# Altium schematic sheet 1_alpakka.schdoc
size 429 x 307 mm; Symbol: Sheet-Symbol_A3; Device: Sheet-Symbol_A3; Company: 嘉立创EDA; Version: V1.0; Page Size: A3; @Project Name: alpakka_qk; @Page Count: 1; @Update Date: 2025-06-17; @Create Date: 2025-06-03; @Schematic Name: alpakka_1; @Page No: 1; @Page Name: alpakka; Title Block Position: 3; Width: 1655; Height: 1170; Region Start: 1; X Region Count: 6; Y Region Count: 4; Blade Width: 10; @Board Name: alpakka_1; @Create Time: 09:50:37; @Update Time: 01:17:22
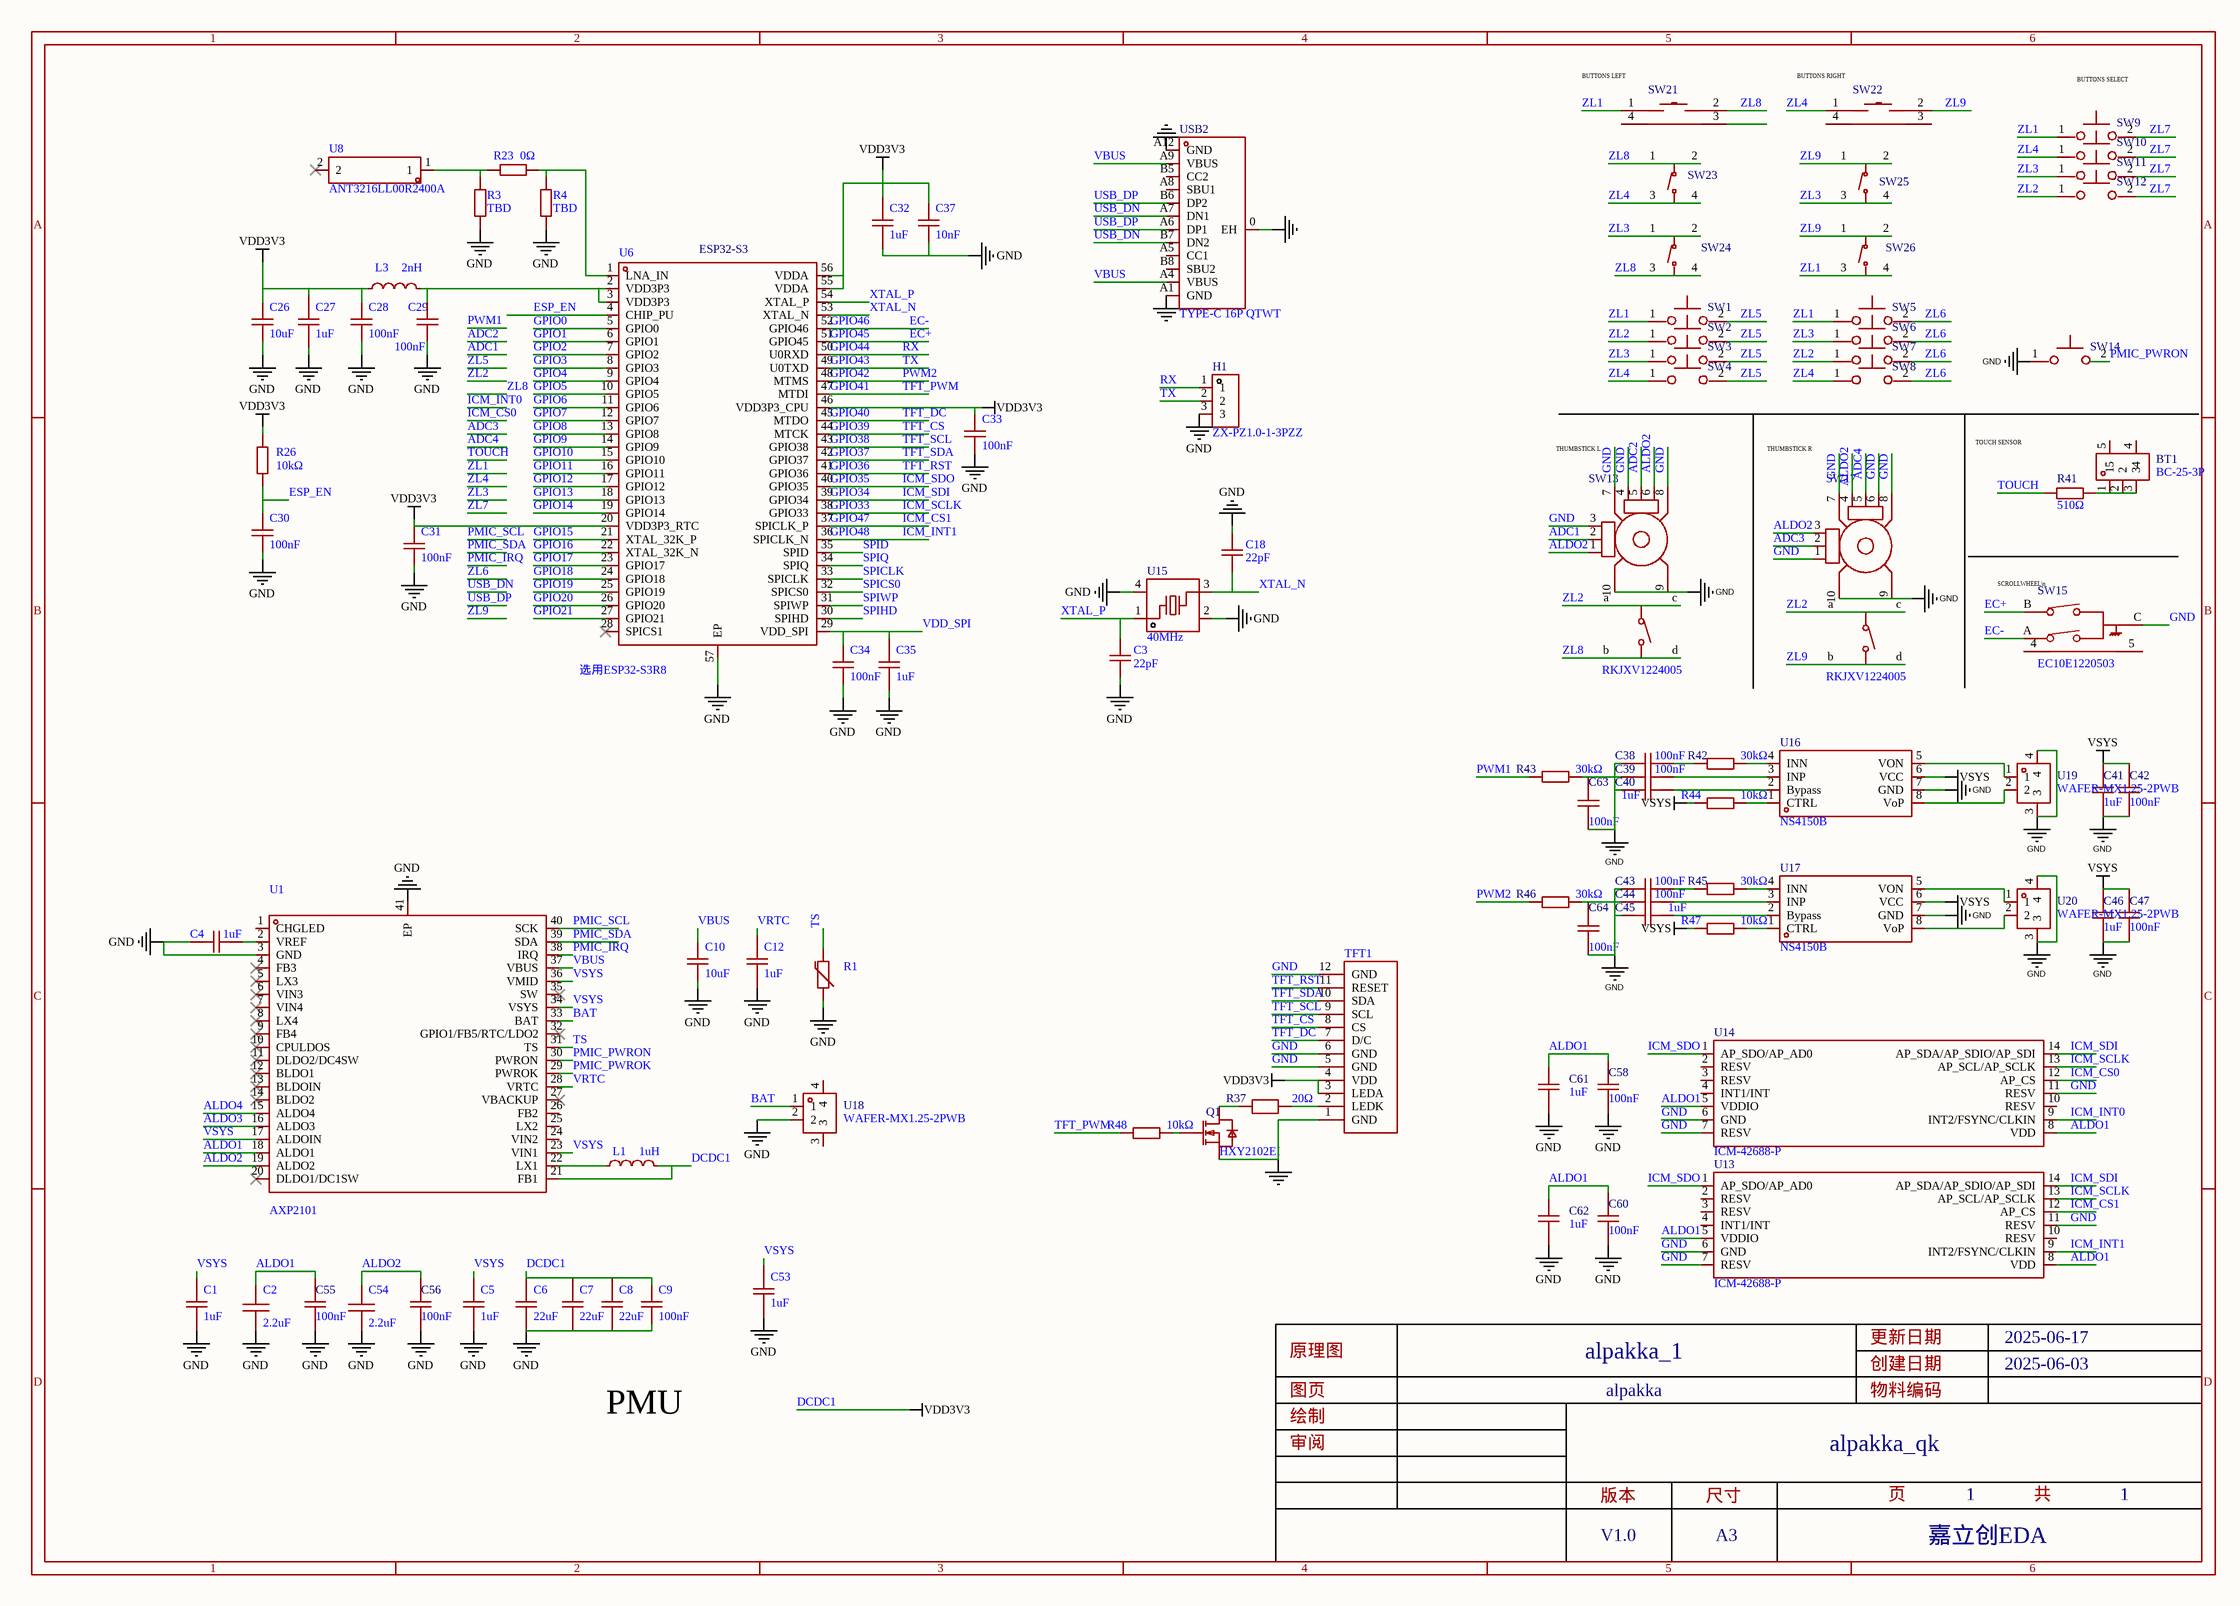
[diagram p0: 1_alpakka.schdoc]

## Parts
BT1  BC-25-3P  [CONN-SMD_BC-25-3P]
C1  1uF  [C0402]
C2  value 2.2uF  [C0402]
C3  22pF  [C0402]
C4  1uF  [C0402]
C5  1uF  [C0402]
C6  22uF  [C0603]
C7  22uF  [C0603]
C8  22uF  [C0603]
C9  100nF  [C0402]
C10  10uF  [C0402]
C12  1uF  [C0402]
C18  22pF  [C0402]
C26  10uF  [C0402]
C27  1uF  [C0402]
C28  100nF  [C0402]
C29  100nF  [C0402]
C30  100nF  [C0402]
C31  100nF  [C0402]
C32  1uF  [C0402]
C33  100nF  [C0402]
C34  100nF  [C0402]
C35  1uF  [C0402]
C37  10nF  [C0402]
C38  100nF  [C0402]
C39  100nF  [C0402]
C40  1uF  [C0402]
C41  1uF  [C0402]
C42  100nF  [C0402]
C43  100nF  [C0402]
C44  100nF  [C0402]
C45  1uF  [C0402]
C46  1uF  [C0402]
C47  100nF  [C0402]
C53  1uF  [C0402]
C54  value 2.2uF  [C0402]
C55  100nF  [C0402]
C56  100nF  [C0402]
C58  100nF  [C0402]
C60  100nF  [C0402]
C61  1uF  [C0402]
C62  1uF  [C0402]
C63  100nF  [C0402]
C64  100nF  [C0402]
H1  ZX-PZ1.0-1-3PZZ  [HDR-TH_3P-P1.00-V-M-3]
L1  1uH  [IND-SMD_L2.5-W2.0_WPN252012H]
L3  2nH  [L0402]
Q1  HXY2102EI  [SOT-323-3_L2.1-W1.3-P1.30-LS2.3-BR]
R1  NCP18XH103F03RB  [R0603]  (value not drawn)
R3  TBD  [R0402]
R4  TBD  [R0402]
R23  0Ω  [R0402]
R26  10kΩ  [R0402]
R37  20Ω  [R0402]
R41  510Ω  [R0402]
R42  30kΩ  [R0402]
R43  30kΩ  [R0402]
R44  10kΩ  [R0402]
R45  30kΩ  [R0402]
R46  30kΩ  [R0402]
R47  10kΩ  [R0402]
R48  10kΩ  [R0402]
SW1  SKPMAME010  [KEY-SMD_2P-L6.0-W6.0-P6.00]  (value not drawn)
SW2  SKPMAME010  [KEY-SMD_2P-L6.0-W6.0-P6.00]  (value not drawn)
SW3  SKPMAME010  [KEY-SMD_2P-L6.0-W6.0-P6.00]  (value not drawn)
SW4  SKPMAME010  [KEY-SMD_2P-L6.0-W6.0-P6.00]  (value not drawn)
SW5  SKPMAME010  [KEY-SMD_2P-L6.0-W6.0-P6.00]  (value not drawn)
SW6  SKPMAME010  [KEY-SMD_2P-L6.0-W6.0-P6.00]  (value not drawn)
SW7  SKPMAME010  [KEY-SMD_2P-L6.0-W6.0-P6.00]  (value not drawn)
SW8  SKPMAME010  [KEY-SMD_2P-L6.0-W6.0-P6.00]  (value not drawn)
SW9  SKPMAME010  [KEY-SMD_2P-L6.0-W6.0-P6.00]  (value not drawn)
SW10  SKPMAME010  [KEY-SMD_2P-L6.0-W6.0-P6.00]  (value not drawn)
SW11  SKPMAME010  [KEY-SMD_2P-L6.0-W6.0-P6.00]  (value not drawn)
SW12  SKPMAME010  [KEY-SMD_2P-L6.0-W6.0-P6.00]  (value not drawn)
SW13  RKJXV1224005  [SW-TH_RKJXV1224005]
SW14  SKPMAME010  [KEY-SMD_2P-L6.0-W6.0-P6.00]  (value not drawn)
SW15  EC10E1220503  [SW-TH_EC10EXXXXXXX]
SW17  RKJXV1224005  [SW-TH_RKJXV1224005]
SW21  SKHHLNA010  [KEY-TH_SKHHLNA010]  (value not drawn)
SW22  SKHHLNA010  [KEY-TH_SKHHLNA010]  (value not drawn)
SW23  TS-1187A-B-A-B  [SW-SMD_4P-L5.1-W5.1-P3.70-LS6.5-TL_H1.5]  (value not drawn)
SW24  TS-1187A-B-A-B  [SW-SMD_4P-L5.1-W5.1-P3.70-LS6.5-TL_H1.5]  (value not drawn)
SW25  TS-1187A-B-A-B  [SW-SMD_4P-L5.1-W5.1-P3.70-LS6.5-TL_H1.5]  (value not drawn)
SW26  TS-1187A-B-A-B  [SW-SMD_4P-L5.1-W5.1-P3.70-LS6.5-TL_H1.5]  (value not drawn)
TFT1  tft  [0.71圆tft]  (value not drawn)
U1  (no value)  [QFN-40_L5.0-W5.0-P0.40-TL-EP3.4]
U6  ESP32-S3  [QFN-56_L7.0-W7.0-P0.40-TL-EP4.0]
U8  ANT3216LL00R2400A  [ANT-SMD_L3.2-W1.6]
U13  ICM-42688-P  [LGA-14_L3.0-W2.5-P0.50-TL]
U14  ICM-42688-P  [LGA-14_L3.0-W2.5-P0.50-TL]
U15  40MHz  [CRYSTAL-SMD_4P-L2.5-W2.0-BL]
U16  NS4150B  [MSOP-8_L3.0-W3.0-P0.65-LS5.0-BL]
U17  NS4150B  [MSOP-8_L3.0-W3.0-P0.65-LS5.0-BL]
U18  WAFER-MX1.25-2PWB  [CONN-SMD_2P-P1.25_XUNPU_WAFER-MX1.25-2PWB]
U19  WAFER-MX1.25-2PWB  [CONN-SMD_2P-P1.25_XUNPU_WAFER-MX1.25-2PWB]
U20  WAFER-MX1.25-2PWB  [CONN-SMD_2P-P1.25_XUNPU_WAFER-MX1.25-2PWB]
USB2  TYPE-C 16P QTWT  [USB-TYPE-C-SMD_TYPE-C-16P-QTWT]

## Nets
DCDC1: C6.2 C7.2 C8.2 C9.2 C26.2 C27.2 C28.2 C31.2 C32.2 C33.2 C37.2 L1.2 L3.1 R26.2 TFT1.3(LEDA) TFT1.4(VDD) U1.21(FB1) U6.20(VDD3P3_RTC) U6.46(VDD3P3_CPU) U6.55(VDDA) U6.56(VDDA)  [also labelled VDD3V3]
GND: C1.1 C2.1 C3.1 C4.1 C5.1 C6.1 C7.1 C8.1 C9.1 C10.1 C12.1 C18.2 C26.1 C27.1 C28.1 C29.1 C30.1 C31.1 C32.1 C33.1 C34.1 C35.1 C37.1 C38.1 C40.2 C41.1 C42.1 C43.1 C45.2 C46.1 C47.1 C53.1 C54.1 C55.1 C56.1 C58.1 C60.1 C61.1 C62.1 C63.1 C64.1 H1.3 Q1.2(S) R1.2 R3.1 R4.1 SW13.3(A) SW13.4(A) SW13.7(GND) SW13.8(GND) SW13.9(GND) SW13.10(GND) SW14.1 SW15.C SW17.1(B) SW17.6(B) SW17.7(GND) SW17.8(GND) SW17.9(GND) SW17.10(GND) TFT1.1(GND) TFT1.5(GND) TFT1.6(GND) TFT1.12(GND) U1.3(GND) U1.41(EP) U6.57(EP) U13.6(GND) U13.7(RESV) U13.11(RESV) U14.6(GND) U14.7(RESV) U14.11(RESV) U15.2(GND) U15.4(GND) U16.7(GND) U17.7(GND) U18.2 U19.3 U19.4 U20.3 U20.4 USB2.0(EH) USB2.A1(GND) USB2.A12(GND)
VSYS: C1.2 C5.2 C41.2 C42.2 C46.2 C47.2 C53.2 R44.1 R47.1 U1.17(ALDOIN) U1.23(VIN1) U1.34(VSYS) U1.36(VMID) U16.6(VCC) U17.6(VCC)
ADC1: SW13.2(DTA)
ADC2: SW13.5(DTA)
ADC3: SW17.2(DTA)
ADC4: SW17.5(DTA)
ALDO1: C2.2 C55.2 C58.2 C60.2 C61.2 C62.2 U1.18(ALDO1) U13.5(VDDIO) U13.8(VDD) U14.5(VDDIO) U14.8(VDD)
ALDO2: C54.2 C56.2 SW13.1(B) SW13.6(B) SW17.3(A) SW17.4(A) U1.19(ALDO2)
ALDO3: U1.16(ALDO3)
ALDO4: U1.15(ALDO4)
BAT: U1.33(BAT) U18.1
EC+: SW15.B U6.51(GPIO45)  [also labelled GPIO45]
EC-: SW15.A U6.52(GPIO46)  [also labelled GPIO46]
ESP_EN: C30.2 R26.1 U6.4(CHIP_PU)
GPIO0: U6.5(GPIO0)
GPIO1: U6.6(GPIO1)
GPIO2: U6.7(GPIO2)
GPIO3: U6.8(GPIO3)
GPIO4: U6.9(GPIO4)
GPIO5: U6.10(GPIO5)
GPIO6: U6.11(GPIO6)
GPIO7: U6.12(GPIO7)
GPIO8: U6.13(GPIO8)
GPIO9: U6.14(GPIO9)
GPIO10: U6.15(GPIO10)
GPIO11: U6.16(GPIO11)
GPIO12: U6.17(GPIO12)
GPIO13: U6.18(GPIO13)
GPIO14: U6.19(GPIO14)
GPIO15: U6.21(XTAL_32K_P)
GPIO16: U6.22(XTAL_32K_N)
GPIO17: U6.23(GPIO17)
GPIO18: U6.24(GPIO18)
GPIO19: U6.25(GPIO19)
GPIO20: U6.26(GPIO20)
GPIO21: U6.27(GPIO21)
GPIO33: U6.38(GPIO33) U13.13(AP_SCL/AP_SCLK) U14.13(AP_SCL/AP_SCLK)  [also labelled ICM_SCLK]
GPIO34: U6.39(GPIO34) U13.14(AP_SDA/AP_SDIO/AP_SDI) U14.14(AP_SDA/AP_SDIO/AP_SDI)  [also labelled ICM_SDI]
GPIO35: U6.40(GPIO35) U13.1(AP_SDO/AP_AD0) U14.1(AP_SDO/AP_AD0)  [also labelled ICM_SDO]
GPIO36: TFT1.11(RESET) U6.41(GPIO36)  [also labelled TFT_RST]
GPIO37: TFT1.10(SDA) U6.42(GPIO37)  [also labelled TFT_SDA]
GPIO38: TFT1.9(SCL) U6.43(GPIO38)  [also labelled TFT_SCL]
GPIO39: TFT1.8(CS) U6.44(MTCK)  [also labelled TFT_CS]
GPIO40: TFT1.7(D/C) U6.45(MTDO)  [also labelled TFT_DC]
GPIO41: R48.1 U6.47(MTDI)  [also labelled TFT_PWM]
GPIO42: R46.1 U6.48(MTMS)  [also labelled PWM2]
GPIO43: H1.2 U6.49(U0TXD)  [also labelled TX]
GPIO44: H1.1 U6.50(U0RXD)  [also labelled RX]
GPIO47: U6.37(SPICLK_P) U13.12(AP_CS)  [also labelled ICM_CS1]
GPIO48: U6.36(SPICLK_N) U13.9(INT2/FSYNC/CLKIN)  [also labelled ICM_INT1]
ICM_CS0: U14.12(AP_CS)
ICM_INT0: U14.9(INT2/FSYNC/CLKIN)
PMIC_IRQ: U1.38(IRQ)
PMIC_PWROK: U1.29(PWROK)
PMIC_PWRON: SW14.2 U1.30(PWRON)
PMIC_SCL: U1.40(SCK)
PMIC_SDA: U1.39(SDA)
PWM1: R43.1
SPICLK: U6.33(SPICLK)
SPICS0: U6.32(SPICS0)
SPID: U6.35(SPID)
SPIHD: U6.30(SPIHD)
SPIQ: U6.34(SPIQ)
SPIWP: U6.31(SPIWP)
TOUCH: R41.2
TS: R1.1 U1.31(TS)
USB_DN: USB2.A7(DN1) USB2.B7(DN2)
USB_DP: USB2.A6(DP1) USB2.B6(DP2)
VBUS: C10.2 U1.37(VBUS) USB2.A4(VBUS) USB2.A9(VBUS)
VDD_SPI: C34.2 C35.2 U6.29(VDD_SPI)
VRTC: C12.2 U1.28(VRTC)
XTAL_N: C18.1 U6.53(XTAL_N) U15.3
XTAL_P: C3.2 U6.54(XTAL_P) U15.1
ZL1: SW1.1 SW5.1 SW9.1 SW21.1 SW26.3(C) SW26.4(D)
ZL2: SW2.1 SW7.1 SW12.1 SW13.a SW13.c SW17.a SW17.c
ZL3: SW3.1 SW6.1 SW11.1 SW24.1(A) SW24.2(B) SW25.3(C) SW25.4(D)
ZL4: SW4.1 SW8.1 SW10.1 SW22.1 SW23.3(C) SW23.4(D)
ZL5: SW1.2 SW2.2 SW3.2 SW4.2
ZL6: SW5.2 SW6.2 SW7.2 SW8.2
ZL7: SW9.2 SW10.2 SW11.2 SW12.2
ZL8: SW13.b SW13.d SW21.2 SW23.1(A) SW23.2(B) SW24.3(C) SW24.4(D)
ZL9: SW17.b SW17.d SW22.2 SW25.1(A) SW25.2(B) SW26.1(A) SW26.2(B)
NetBT1_1: BT1.1 BT1.2 BT1.3 R41.1
NetC4_2: C4.2 U1.2(VREF)
NetC29_2: C29.2 L3.2 U6.2(VDD3P3) U6.3(VDD3P3)
NetC38_2: C38.2 R42.1
NetC39_1: C39.1 C63.2 R43.2
NetC39_2: C39.2 U16.3(INP)
NetC40_1: C40.1 U16.2(Bypass)
NetC43_2: C43.2 R45.1
NetC44_1: C44.1 C64.2 R46.2
NetC44_2: C44.2 U17.3(INP)
NetC45_1: C45.1 U17.2(Bypass)
NetL1_1: L1.1 U1.22(LX1)
NetQ1_1: Q1.1(G) R48.2
NetQ1_3: Q1.3(D) R37.1
NetR3_2: R3.2 R23.1 U8.1
NetR4_2: R4.2 R23.2 U6.1(LNA_IN)
NetR37_2: R37.2 TFT1.2(LEDK)
NetR42_2: R42.2 U16.4(INN)
NetR44_2: R44.2 U16.1(CTRL)
NetR45_2: R45.2 U17.4(INN)
NetR47_2: R47.2 U17.1(CTRL)
NetU16_5: U16.5(VON) U19.1
NetU16_8: U16.8(VoP) U19.2
NetU17_5: U17.5(VON) U20.1
NetU17_8: U17.8(VoP) U20.2

Not connected (* = marked no-connect by the designer): BT1 4 5; SW15 4 5; SW21 3 4; SW22 3 4; U1 1(CHGLED) 4(FB3)* 5(LX3)* 6(VIN3)* 7(VIN4)* 8(LX4)* 9(FB4)* 10(CPULDOS)* 11(DLDO2/DC4SW)* 12(BLDO1)* 13(BLDOIN)* 14(BLDO2)* 20(DLDO1/DC1SW)* 24(VIN2) 25(LX2) 26(FB2) 27(VBACKUP)* 32(GPIO1/FB5/RTC/LDO2)* 35(SW)*; U6 28(SPICS1)*; U8 2*; U13 2(RESV) 3(RESV) 4(INT1/INT) 10(RESV); U14 2(RESV) 3(RESV) 4(INT1/INT) 10(RESV); U18 3 4; USB2 A5(CC1) A8(SBU1) B5(CC2) B8(SBU2)

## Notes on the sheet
- (near SW21) BUTTONS LEFT
- (near SW22) BUTTONS RIGHT
- BUTTONS SELECT
- TOUCH SENSOR
- (near SW13) THUMBSTICK L
- THUMBSTICK R
- (near SW15) SCROLLWHEEL\n
- (near U6) 选用ESP32-S3R8
- PMU

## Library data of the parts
BT1 = BC-25-3P: Manufacturer: 韩国韩荣; Add into BOM: yes
C1 C4 C5 C12 C27 C32 C35 C40 C41 C45 C46 C53 C61 C62 = CL05A105KA5NQNC: Manufacturer: SAMSUNG(三星); Add into BOM: yes; Tolerance: ±10%; Voltage Rated: 25V; Temperature Coefficient: X5R
C2 C54 = CL05A225MQ5NSNC: Manufacturer: SAMSUNG(三星); Add into BOM: yes; Tolerance: ±20%; Voltage Rated: 6.3V; Temperature Coefficient: X5R
C3 C18 = 0402CG220J500NT: Manufacturer: FH(风华); Add into BOM: yes; Tolerance: ±5%; Voltage Rated: 50V; Temperature Coefficient: C0G
C6-C8 = CL10A226MQ8NRNC: Manufacturer: SAMSUNG(三星); Add into BOM: yes; Tolerance: ±20%; Voltage Rated: 6.3V; Temperature Coefficient: X5R
C9 C28-C31 C33 C34 = CL05B104KO5NNNC: Manufacturer: SAMSUNG(三星); Add into BOM: yes; Tolerance: ±10%; Voltage Rated: 16V; Temperature Coefficient: X7R
C10 C26 = CL05A106MQ5NUNC: Manufacturer: SAMSUNG(三星); Add into BOM: yes; Tolerance: ±20%; Voltage Rated: 6.3V; Temperature Coefficient: X5R
C37 = CL05B103KB5NNNC: Manufacturer: SAMSUNG(三星); Add into BOM: yes; Tolerance: ±10%; Voltage Rated: 50V; Temperature Coefficient: X7R
C38 C39 C42-C44 C47 C55 C56 C58 C60 C63 C64 = CL05B104KB54PNC: Manufacturer: SAMSUNG(三星); Add into BOM: yes; Tolerance: ±10%; Voltage Rated: 50V; Temperature Coefficient: X7R
H1 = ZX-PZ1.0-1-3PZZ: Manufacturer: Megastar(兆星); Add into BOM: yes; Pin Structure: 1x3P; Pitch: 1mm; Circluar Pins/Square Pins: 方针; Current Rating: 750mA
L1 = WPN252012H1R0MT: Manufacturer: Sunlord(顺络); Add into BOM: yes; Tolerance: ±20%; Rated Current: 3A; DC Resistance (DCR): 54mΩ
L3 = LQG15HS2N0S02D: Manufacturer: muRata(村田); Add into BOM: yes; Tolerance: ±0.3nH; Rated Current: 900mA; DC Resistance (DCR): 90mΩ; Q @ Freq: 8@100MHz; Frequency - Self Resonant: 6GHz
Q1 = HXY2102EI: Manufacturer: HXY MOSFET(华轩阳电子); Add into BOM: yes; Type: 1个N沟道; Drain to Source Voltage: 20V; Current - Continuous Drain(Id): 2A; RDS(on): 85mΩ@2.5V,0.3A; Pd - Power Dissipation: 300mW; Gate Threshold Voltage (Vgs(th)@Id): 1V; Input Capacitance(Ciss@Vds): 300pF@10V; Reverse Transfer Capacitance (Crss@Vds): 80pF
R1 = NCP18XH103F03RB: Manufacturer: muRata(村田); Add into BOM: yes; Resistance @ 25℃: 10kΩ; Resistance Tolerance: ±1%; B Constant (25℃/50℃): 3380K; Power: 100mW; Steady State Current (Max): 310uA; B Constant (25℃/85℃): 3334K; B Constant (25℃/100℃): 3455K
R3 R4 = 0402WGF0000TCE: Manufacturer: UNI-ROYAL(厚声); Add into BOM: yes; Tolerance: ±1%; Power(Watts): 1/16W; Temperature Coefficient: ±800ppm/; Overload Voltage (Max): 50V; Check: false
R23 = 0402WGF0000TCE: Manufacturer: UNI-ROYAL(厚声); Add into BOM: yes; Tolerance: ±1%; Power(Watts): 1/16W; Temperature Coefficient: ±800ppm/; Overload Voltage (Max): 50V
R26 R44 R47 R48 = 0402WGF1002TCE: Manufacturer: UNI-ROYAL(厚声); Add into BOM: yes; Tolerance: ±1%; Power(Watts): 62.5mW; Temperature Coefficient: ±100ppm/℃; Overload Voltage (Max): 50V
R37 = AF0402FR-0720RL: Manufacturer: YAGEO(国巨); Add into BOM: yes; Tolerance: ±1%; Power(Watts): 62.5mW; Overload Voltage (Max): 50V; Temperature Coefficient: ±100ppm/℃
R41 = 0402WGF5100TCE: Manufacturer: UNI-ROYAL(厚声); Add into BOM: yes; Tolerance: ±1%; Power(Watts): 62.5mW; Overload Voltage (Max): 50V; Temperature Coefficient: ±100ppm/℃
R42 R43 R45 R46 = 0402WGF3002TCE: Manufacturer: UNI-ROYAL(厚声); Add into BOM: yes; Tolerance: ±1%; Power(Watts): 62.5mW; Overload Voltage (Max): 50V; Temperature Coefficient: ±100ppm/℃
SW1-SW12 SW14 = SKPMAME010: Manufacturer: ALPSALPINE(阿尔卑斯阿尔派); Add into BOM: yes; Circuit: 单刀单掷; Actuator Style: 圆形按钮; Switch Length: 6mm; Switch Width: 5.9mm; Switch Height: 5mm; Contact Current: 50mA; Voltage Rating (DC): 16V
SW13 SW17 = RKJXV1224005: Manufacturer: ALPSALPINE(阿尔卑斯阿尔派); Add into BOM: yes
SW15 = EC10E1220503: Manufacturer: ALPSALPINE(阿尔卑斯阿尔派); Add into BOM: yes
SW21 SW22 = SKHHLNA010: Manufacturer: ALPSALPINE(阿尔卑斯阿尔派); Add into BOM: yes; Circuit: 单刀单掷; Actuator Style: 圆形按钮; Switch Length: 6.2mm; Switch Height: 3.85mm; Contact Current: 50mA; Voltage Rating (DC): 12V
SW23-SW26 = TS-1187A-B-A-B: Manufacturer: XKB Connectivity(中国星坤); Add into BOM: yes; Circuit: 单刀单掷; Actuator Style: 圆形按钮; Operating Force: 160gf; Switch Length: 5.1mm; Switch Height: 1.5mm; Strike Gundam: 不带; Contact Current: 50mA; Voltage Rating (DC): 12V; Actuator/Cap Color: 金色; With Lamp: 无; Mechanical Life: 10万次
TFT1 = 0.71园tft: Symbol: TFT_1.28_GC9A01_CB0.8; Add into BOM: yes; Check: false
U1 = AXP2101: Manufacturer: Allwinner(全志); Add into BOM: yes; Check: false
U6 = ESP32-S3: Manufacturer: ESPRESSIF 乐鑫; Add into BOM: yes; Check: false
U8 = ANT3216LL00R2400A: Manufacturer: YAGEO(国巨); Add into BOM: yes
U13 U14 = ICM-42688-P: Manufacturer: TDK InvenSense(应美盛); Add into BOM: yes; Sensor Type: 加速度计陀螺仪
U15 = X252040MMB4SI: Manufacturer: YXC(扬兴晶振); Add into BOM: yes; Normal temperature Frequency Tolerance: ±10ppm; Load Capacitance: 10pF; Frequency Stability: ±20ppm
U16 U17 = NS4150B_C189961: Manufacturer: Nsiway(纳芯威); Symbol: NS4150; Add into BOM: yes; Type of Power Amplifier: D类功放; Output Power: 3Wx1@4Ω; Supply Voltage: 3V~5.25V
U18-U20 = WAFER-MX1.25-2PWB: Manufacturer: XUNPU(讯普); Add into BOM: yes; Pins Structure: 1x2P; Pitch: 1.25mm; Reference Series: PicoBlade(MX 1.25); Number of PINs Per Row: 2; Current Rating: 1A; Voltage Rating: 125V; Plastic Material: LCP; Supplementary Features: 辅助焊脚; Z-Height of the Board: 3.6mm; X-Length of Bottom Edge on Board (Spacing Line): 7.5mm; Y-Width of Bottom Edge on Board: 5.25mm
USB2 = TYPE-C 16P QTWT: Manufacturer: SHOU HAN(首韩); Add into BOM: yes; Gender: 母; Number of Ports: 1; Current Rating - Power (Max): 3A; Rated Voltage (Max): 5V; Connect-Disconnect Life: 1万次; Core Colour: 黑色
